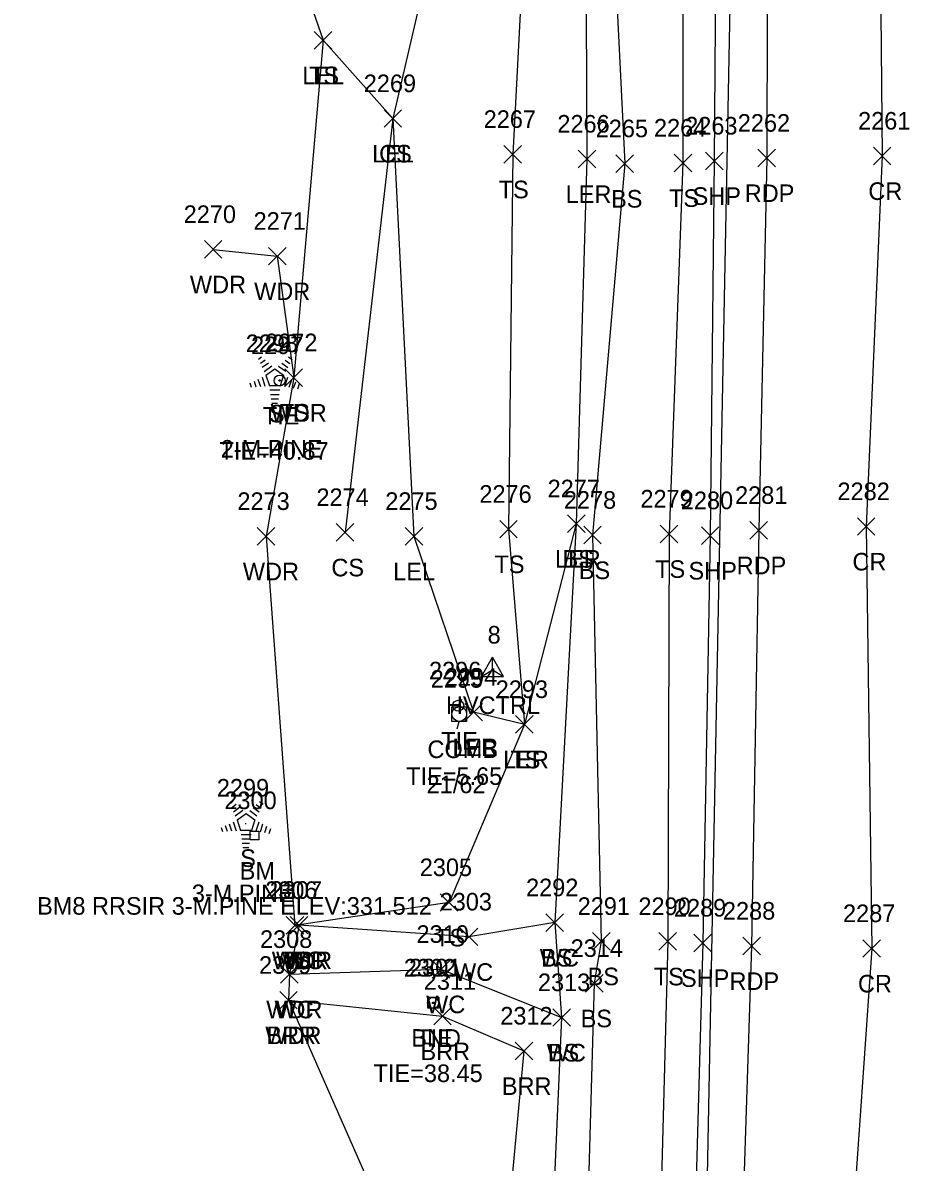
# Model space of a CAD drawing. Extents: x 1462089 to 1464015, y 730534 to 736144.
# Drawn here: x 1463126.5 to 1463227.3, y 734283.7 to 734413.3 of the extents above; entities that cross this region are included whole.
import ezdxf

# ---------------------------------------------------------------- set-up
doc = ezdxf.new("R2010")
doc.units = 0
for name, color, linetype in [('C_A', 7, 'Continuous'), ('C_C', 7, 'Continuous'), ('C_I', 7, 'Continuous'), ('CBP', 7, 'Continuous'), ('CPBM', 7, 'Continuous'), ('CPSM', 7, 'Continuous'), ('DCP', 7, 'Continuous'), ('L_A', 7, 'Continuous'), ('L_C', 7, 'Continuous'), ('L_I', 7, 'Continuous'), ('L_TIC', 7, 'Continuous'), ('LABL', 7, 'Continuous'), ('LARO', 7, 'Continuous'), ('LAWA', 7, 'Continuous'), ('LAWE', 7, 'Continuous'), ('LELB', 7, 'Continuous'), ('LTC', 7, 'Continuous'), ('M_A', 7, 'Continuous'), ('M_I', 7, 'Continuous'), ('MHBP', 7, 'Continuous'), ('P_A', 7, 'Continuous'), ('P_I', 7, 'Continuous'), ('P_TIC', 7, 'Continuous'), ('PET', 7, 'Continuous'), ('PRC', 7, 'Continuous'), ('PSP', 7, 'Continuous'), ('U_A', 7, 'Continuous'), ('U_C', 7, 'Continuous'), ('U_I', 7, 'Continuous'), ('UP', 7, 'Continuous')]:
    doc.layers.add(name, color=color, linetype=linetype)

msp = doc.modelspace()

# ---------------------------------------------------------------- linework, layer by layer
at = {"layer": 'CBP'}
for centre, radius in [((1463155.69, 734372.59), 0.625), ((1463155.69, 734372.59), 0.0833), ((1463175.99, 734335.61), 0.625), ((1463175.99, 734335.61), 0.0833), ((1463173.14, 734301.82), 0.625), ((1463173.14, 734301.82), 0.0833)]:
    msp.add_circle(centre, radius, dxfattribs=at)
at = {"layer": 'CPBM'}
for p, q in [((1463152.32, 734320.35), (1463152.32, 734321.35)), ((1463152.32, 734321.35), (1463153.32, 734321.35)), ((1463152.82, 734320.85), (1463152.82, 734320.85)), ((1463152.82, 734320.85), (1463152.82, 734320.85)), ((1463153.32, 734321.35), (1463153.32, 734320.35)), ((1463153.32, 734320.35), (1463152.32, 734320.35))]:
    msp.add_line(p, q, dxfattribs=at)
at = {"layer": 'CPSM'}
for p, q in [((1463178.66, 734338.95), (1463179.91, 734341.12)), ((1463181.16, 734338.95), (1463179.91, 734341.12)), ((1463179.91, 734339.68), (1463179.91, 734341.12)), ((1463178.66, 734338.95), (1463179.91, 734339.68)), ((1463178.66, 734338.95), (1463181.16, 734338.95)), ((1463179.91, 734339.68), (1463179.91, 734339.68)), ((1463179.91, 734339.68), (1463181.16, 734338.95))]:
    msp.add_line(p, q, dxfattribs=at)
at = {"layer": 'DCP'}
msp.add_lwpolyline([(1463208.21, 734483.63), (1463199.06, 734012.28)], dxfattribs=at)
at = {"layer": 'L_TIC'}
for points in [[(1463159.62, 734410.28), (1463161.62, 734412.28)], [(1463161.62, 734410.28), (1463159.62, 734412.28)], [(1463159.62, 734410.28), (1463161.62, 734412.28)], [(1463161.62, 734410.28), (1463159.62, 734412.28)], [(1463167.56, 734401.38), (1463169.56, 734403.38)], [(1463169.56, 734401.38), (1463167.56, 734403.38)], [(1463167.56, 734401.38), (1463169.56, 734403.38)], [(1463169.56, 734401.38), (1463167.56, 734403.38)], [(1463181.19, 734397.31), (1463183.19, 734399.31)], [(1463183.19, 734397.31), (1463181.19, 734399.31)], [(1463189.63, 734396.78), (1463191.63, 734398.78)], [(1463191.63, 734396.78), (1463189.63, 734398.78)], [(1463193.94, 734396.25), (1463195.94, 734398.25)], [(1463195.94, 734396.25), (1463193.94, 734398.25)], [(1463200.56, 734396.33), (1463202.56, 734398.33)], [(1463202.56, 734396.33), (1463200.56, 734398.33)], [(1463147.12, 734386.5), (1463149.12, 734388.5)], [(1463149.12, 734386.5), (1463147.12, 734388.5)], [(1463154.42, 734385.73), (1463156.42, 734387.73)], [(1463156.42, 734385.73), (1463154.42, 734387.73)], [(1463156.29, 734371.92), (1463158.29, 734373.92)], [(1463158.29, 734371.92), (1463156.29, 734373.92)], [(1463156.29, 734371.92), (1463158.29, 734373.92)], [(1463158.29, 734371.92), (1463156.29, 734373.92)], [(1463180.71, 734354.69), (1463182.71, 734356.69)], [(1463182.71, 734354.69), (1463180.71, 734356.69)], [(1463188.42, 734355.31), (1463190.42, 734357.31)], [(1463190.42, 734355.31), (1463188.42, 734357.31)], [(1463188.42, 734355.31), (1463190.42, 734357.31)], [(1463190.42, 734355.31), (1463188.42, 734357.31)], [(1463153.14, 734353.87), (1463155.14, 734355.87)], [(1463155.14, 734353.87), (1463153.14, 734355.87)], [(1463162.13, 734354.32), (1463164.13, 734356.32)], [(1463164.13, 734354.32), (1463162.13, 734356.32)], [(1463169.96, 734353.88), (1463171.96, 734355.88)], [(1463171.96, 734353.88), (1463169.96, 734355.88)], [(1463190.27, 734354.01), (1463192.27, 734356.01)], [(1463192.27, 734354.01), (1463190.27, 734356.01)], [(1463198.98, 734354.15), (1463200.98, 734356.15)], [(1463200.98, 734354.15), (1463198.98, 734356.15)], [(1463176.74, 734333.88), (1463178.74, 734335.88)], [(1463178.74, 734333.88), (1463176.74, 734335.88)], [(1463176.74, 734333.88), (1463178.74, 734335.88)], [(1463178.74, 734333.88), (1463176.74, 734335.88)], [(1463182.52, 734332.49), (1463184.52, 734334.49)], [(1463184.52, 734332.49), (1463182.52, 734334.49)], [(1463182.52, 734332.49), (1463184.52, 734334.49)], [(1463184.52, 734332.49), (1463182.52, 734334.49)], [(1463173.96, 734312.24), (1463175.96, 734314.24)], [(1463175.96, 734312.24), (1463173.96, 734314.24)], [(1463156.43, 734309.64), (1463158.43, 734311.64)], [(1463158.43, 734309.64), (1463156.43, 734311.64)], [(1463156.43, 734309.64), (1463158.43, 734311.64)], [(1463158.43, 734309.64), (1463156.43, 734311.64)], [(1463156.9, 734309.66), (1463158.9, 734311.66)], [(1463158.9, 734309.66), (1463156.9, 734311.66)], [(1463156.9, 734309.66), (1463158.9, 734311.66)], [(1463158.9, 734309.66), (1463156.9, 734311.66)], [(1463185.97, 734309.95), (1463187.97, 734311.95)], [(1463187.97, 734309.95), (1463185.97, 734311.95)], [(1463185.97, 734309.95), (1463187.97, 734311.95)], [(1463187.97, 734309.95), (1463185.97, 734311.95)], [(1463176.22, 734308.33), (1463178.22, 734310.33)], [(1463178.22, 734308.33), (1463176.22, 734310.33)], [(1463191.27, 734307.83), (1463193.27, 734309.83)], [(1463193.27, 734307.83), (1463191.27, 734309.83)], [(1463198.83, 734307.81), (1463200.83, 734309.81)], [(1463200.83, 734307.81), (1463198.83, 734309.81)], [(1463173.03, 734304.65), (1463175.03, 734306.65)], [(1463175.03, 734304.65), (1463173.03, 734306.65)], [(1463155.79, 734304.07), (1463157.79, 734306.07)], [(1463157.79, 734304.07), (1463155.79, 734306.07)], [(1463155.79, 734304.07), (1463157.79, 734306.07)], [(1463157.79, 734304.07), (1463155.79, 734306.07)], [(1463190.47, 734303.05), (1463192.47, 734305.05)], [(1463192.47, 734303.05), (1463190.47, 734305.05)], [(1463155.69, 734301.13), (1463157.69, 734303.13)], [(1463157.69, 734301.13), (1463155.69, 734303.13)], [(1463155.69, 734301.13), (1463157.69, 734303.13)], [(1463157.69, 734301.13), (1463155.69, 734303.13)], [(1463173.21, 734299.31), (1463175.21, 734301.31)], [(1463175.21, 734299.31), (1463173.21, 734301.31)], [(1463186.75, 734299.16), (1463188.75, 734301.16)], [(1463188.75, 734299.16), (1463186.75, 734301.16)], [(1463186.75, 734299.16), (1463188.75, 734301.16)], [(1463188.75, 734299.16), (1463186.75, 734301.16)], [(1463182.47, 734295.36), (1463184.47, 734297.36)], [(1463184.47, 734295.36), (1463182.47, 734297.36)]]:
    msp.add_lwpolyline(points, dxfattribs=at)
at = {"layer": 'LABL'}
msp.add_lwpolyline([(1463156.69, 734302.13), (1463174.21, 734300.31), (1463183.47, 734296.36), (1463181.09, 734271.11), (1463181.93, 734223), (1463178.85, 734177.9), (1463178.45, 734143.72), (1463169.26, 734138.24), (1463157.46, 734125.42), (1463144.39, 734102.43)], dxfattribs=at)
at = {"layer": 'LARO'}
for points in [[(1463147.4, 734662.67), (1463157.46, 734664.77), (1463169.03, 734661.82), (1463169.68, 734646.7), (1463182.2, 734627.23), (1463187.8, 734600.17), (1463188.26, 734544.08), (1463183.83, 734520.03), (1463176.69, 734515.3), (1463169.22, 734500.9), (1463169.8, 734483.47), (1463167.02, 734456.28), (1463176.84, 734437.92), (1463184.12, 734434.72), (1463190.48, 734431.13), (1463190.63, 734397.78), (1463189.42, 734356.31), (1463183.52, 734333.49), (1463177.74, 734334.88)], [(1463143.95, 734520.52), (1463142.85, 734496.85), (1463155.61, 734488.43), (1463144.85, 734456.52), (1463160.62, 734411.28), (1463168.56, 734402.38), (1463170.96, 734354.88), (1463177.74, 734334.88)]]:
    msp.add_lwpolyline(points, dxfattribs=at)
at = {"layer": 'LAWA'}
msp.add_lwpolyline([(1463148.12, 734387.5), (1463155.42, 734386.73), (1463157.29, 734372.92), (1463154.14, 734354.87), (1463157.43, 734310.64), (1463157.9, 734310.66), (1463156.79, 734305.07), (1463156.69, 734302.13), (1463169.77, 734272.41), (1463157.85, 734224.06), (1463161.29, 734206.99), (1463143.39, 734203.85), (1463126.47, 734185.65), (1463137.14, 734130.78), (1463144.39, 734102.43), (1463152.2, 734075.02), (1463142.97, 734026.1), (1463140.98, 733987.76), (1463154.22, 733983.37), (1463156.8, 733967.66), (1463142.94, 733971.97)], dxfattribs=at)
at = {"layer": 'LAWE'}
for points in [[(1463186.97, 734310.95), (1463177.22, 734309.33), (1463157.9, 734310.66)], [(1463156.79, 734305.07), (1463174.03, 734305.65), (1463187.75, 734300.16)]]:
    msp.add_lwpolyline(points, dxfattribs=at)
at = {"layer": 'LELB'}
for points in [[(1463188.62, 734799.74), (1463189.23, 734750.9), (1463189.74, 734700.69), (1463192.42, 734649.85), (1463191, 734599.71), (1463193.42, 734544.23), (1463196.71, 734496.43), (1463196.17, 734489.61), (1463194.29, 734482.61), (1463193.43, 734453.88), (1463193.28, 734430.96), (1463194.94, 734397.25), (1463191.27, 734355.01), (1463192.27, 734308.83), (1463191.47, 734304.05), (1463190.52, 734270.68), (1463189.48, 734220.76), (1463188.7, 734176.43), (1463187.31, 734119.86), (1463187.93, 734073.26), (1463188.66, 734026.72), (1463187.05, 734012.08), (1463189.61, 733964.42)], [(1463195.34, 734798.31), (1463197.41, 734750.53), (1463197.46, 734700.17), (1463198.58, 734651.04), (1463199.21, 734598.9), (1463200.2, 734544.23), (1463202.14, 734496.43), (1463201.54, 734449.41), (1463201.56, 734397.33), (1463199.98, 734355.15), (1463199.83, 734308.81), (1463198.79, 734268.98), (1463198.11, 734220.24), (1463196.93, 734175.14), (1463195.85, 734119.26), (1463193.82, 734072.07), (1463194.4, 734026.45), (1463194.59, 734010.55), (1463192.58, 733964.29), (1463190.31, 733917.66)], [(1463178.57, 734776.69), (1463177.31, 734753.5), (1463179.18, 734700.8), (1463180.32, 734646.66), (1463182.2, 734627.23), (1463182.7, 734603.79), (1463184.28, 734596.53), (1463183.86, 734543.96), (1463183.83, 734520.03), (1463183.36, 734481.92), (1463182.16, 734457.78), (1463184.12, 734434.72), (1463182.19, 734398.31), (1463181.71, 734355.69), (1463183.52, 734333.49), (1463174.96, 734313.24), (1463157.43, 734310.64)], [(1463182.7, 734603.79), (1463180.76, 734596.84), (1463172.86, 734543.3), (1463176.69, 734515.3), (1463177.02, 734482.59), (1463176.19, 734457.19), (1463176.84, 734437.92), (1463168.56, 734402.38), (1463163.13, 734355.32)], [(1463160.62, 734411.28), (1463157.29, 734372.92)], [(1463189.42, 734356.31), (1463186.97, 734310.95), (1463187.75, 734300.16), (1463186.45, 734270.72), (1463186.26, 734221.6), (1463184.59, 734177.13), (1463184.44, 734120.4), (1463183.66, 734072.96), (1463185.97, 734027.2), (1463185.64, 734017.64), (1463181.98, 734013.82), (1463182.38, 734009.37), (1463185.74, 734008.63), (1463186.1, 733963.74), (1463187.32, 733917.63), (1463182.85, 733886.22), (1463182.95, 733866.86), (1463182.65, 733862.97), (1463181.59, 733831.54)]]:
    msp.add_lwpolyline(points, dxfattribs=at)
at = {"layer": 'LTC'}
for p, q in [((1463153.28, 734375.03), (1463153.63, 734375.29)), ((1463153.49, 734374.56), (1463154.02, 734374.95)), ((1463156.31, 734374.92), (1463156.86, 734374.52)), ((1463156.68, 734375.27), (1463157.1, 734374.97)), ((1463153.7, 734374.1), (1463154.4, 734374.61)), ((1463153.91, 734373.63), (1463154.79, 734374.27)), ((1463154.13, 734373.18), (1463155.15, 734373.91)), ((1463155.15, 734373.91), (1463156.14, 734373.19)), ((1463155.57, 734374.22), (1463156.37, 734373.64)), ((1463155.94, 734374.57), (1463156.62, 734374.08)), ((1463152.31, 734372.31), (1463152.46, 734371.84)), ((1463152.77, 734372.53), (1463152.98, 734371.87)), ((1463153.22, 734372.74), (1463153.49, 734371.91)), ((1463153.68, 734372.96), (1463154.01, 734371.94)), ((1463154.13, 734373.18), (1463154.52, 734371.98)), ((1463156.14, 734373.19), (1463155.75, 734371.98)), ((1463156.58, 734372.92), (1463156.24, 734371.88)), ((1463157.02, 734372.67), (1463156.74, 734371.78)), ((1463157.47, 734372.42), (1463157.23, 734371.69)), ((1463155.75, 734371.98), (1463154.52, 734371.98)), ((1463155.71, 734371.48), (1463154.57, 734371.48)), ((1463155.63, 734370.98), (1463154.64, 734370.98)), ((1463157.91, 734372.17), (1463157.73, 734371.59)), ((1463155.55, 734370.48), (1463154.71, 734370.48)), ((1463155.46, 734369.98), (1463154.79, 734369.98)), ((1463150.01, 734324.49), (1463150.36, 734324.75)), ((1463150.22, 734324.02), (1463150.75, 734324.41)), ((1463153.03, 734324.38), (1463153.58, 734323.98)), ((1463153.4, 734324.73), (1463153.82, 734324.43)), ((1463150.43, 734323.56), (1463151.13, 734324.07)), ((1463150.64, 734323.09), (1463151.51, 734323.73)), ((1463150.86, 734322.64), (1463151.87, 734323.37)), ((1463151.87, 734323.37), (1463152.87, 734322.65)), ((1463152.29, 734323.69), (1463153.1, 734323.1)), ((1463152.66, 734324.03), (1463153.34, 734323.54)), ((1463149.04, 734321.77), (1463149.19, 734321.3)), ((1463149.49, 734321.99), (1463149.71, 734321.33)), ((1463149.95, 734322.2), (1463150.22, 734321.37)), ((1463150.41, 734322.42), (1463150.74, 734321.4)), ((1463150.86, 734322.64), (1463151.25, 734321.44)), ((1463152.87, 734322.65), (1463152.48, 734321.44)), ((1463153.31, 734322.38), (1463152.97, 734321.34)), ((1463153.75, 734322.13), (1463153.46, 734321.24)), ((1463154.2, 734321.88), (1463153.96, 734321.15)), ((1463152.48, 734321.44), (1463151.25, 734321.44)), ((1463152.44, 734320.94), (1463151.29, 734320.94)), ((1463152.36, 734320.44), (1463151.37, 734320.44)), ((1463154.64, 734321.63), (1463154.45, 734321.05)), ((1463152.27, 734319.94), (1463151.44, 734319.94)), ((1463152.19, 734319.44), (1463151.51, 734319.44))]:
    msp.add_line(p, q, dxfattribs=at)
at = {"layer": 'MHBP'}
msp.add_lwpolyline([(1463172.55, 734302.47), (1463173.8, 734302.47), (1463173.8, 734301.22), (1463172.55, 734301.22)], close=True, dxfattribs=at)
msp.add_circle((1463173.17, 734301.84), 0.0833, dxfattribs=at)
at = {"layer": 'P_TIC'}
for points in [[(1463204.12, 734396.56), (1463206.12, 734398.56)], [(1463206.12, 734396.56), (1463204.12, 734398.56)], [(1463210.09, 734396.88), (1463212.09, 734398.88)], [(1463212.09, 734396.88), (1463210.09, 734398.88)], [(1463223.21, 734397.12), (1463225.21, 734399.12)], [(1463225.21, 734397.12), (1463223.21, 734399.12)], [(1463221.39, 734354.99), (1463223.39, 734356.99)], [(1463223.39, 734354.99), (1463221.39, 734356.99)], [(1463203.65, 734353.96), (1463205.65, 734355.96)], [(1463205.65, 734353.96), (1463203.65, 734355.96)], [(1463209.17, 734354.56), (1463211.17, 734356.56)], [(1463211.17, 734354.56), (1463209.17, 734356.56)], [(1463202.8, 734307.64), (1463204.8, 734309.64)], [(1463204.8, 734307.64), (1463202.8, 734309.64)], [(1463208.36, 734307.29), (1463210.36, 734309.29)], [(1463210.36, 734307.29), (1463208.36, 734309.29)], [(1463222.02, 734307.01), (1463224.02, 734309.01)], [(1463224.02, 734307.01), (1463222.02, 734309.01)]]:
    msp.add_lwpolyline(points, dxfattribs=at)
at = {"layer": 'PET'}
msp.add_lwpolyline([(1463204.71, 734797.84), (1463205.78, 734749.61), (1463206.44, 734700.37), (1463207.91, 734653.17), (1463208.96, 734598.74), (1463210.17, 734544.3), (1463210.74, 734497.48), (1463211.21, 734449.42), (1463211.09, 734397.88), (1463210.17, 734355.56), (1463209.36, 734308.29), (1463208.04, 734267.48), (1463207.44, 734219.42), (1463205.88, 734174.98), (1463204.27, 734119.17), (1463203.71, 734073.3), (1463203.1, 734019.17), (1463201.74, 733964.33)], dxfattribs=at)
at = {"layer": 'PRC'}
msp.add_lwpolyline([(1463217.11, 734797.78), (1463218.92, 734749.04), (1463217.99, 734700.8), (1463220.46, 734654.03), (1463220.81, 734599.08), (1463223.52, 734546), (1463222.51, 734496.9), (1463223.72, 734451.06), (1463224.21, 734398.12), (1463222.39, 734355.99), (1463223.02, 734308.01), (1463220.18, 734267.3), (1463222.37, 734218.38), (1463218.64, 734173.78), (1463216.82, 734118.18), (1463215.37, 734073.48), (1463215.19, 734017.4), (1463213.25, 733964.17)], dxfattribs=at)
at = {"layer": 'PSP'}
msp.add_lwpolyline([(1463199.84, 734798.03), (1463200.23, 734750.21), (1463201.04, 734700.38), (1463202.35, 734652.01), (1463203.05, 734599.23), (1463204.56, 734544.33), (1463205.11, 734496.59), (1463205.48, 734449.4), (1463205.12, 734397.56), (1463204.65, 734354.96), (1463203.8, 734308.64), (1463202.66, 734268.21), (1463201.74, 734219.53), (1463200.48, 734174.61), (1463198.94, 734119.22), (1463197.74, 734073.05), (1463196.88, 734018.95), (1463195.12, 733964.59)], dxfattribs=at)
at = {"layer": 'UP'}
for p, q in [((1463176.37, 734336.32), (1463176.12, 734335.49)), ((1463175.28, 734333.82), (1463175.28, 734335.49)), ((1463175.28, 734335.49), (1463176.95, 734335.49)), ((1463176.95, 734335.49), (1463176.95, 734333.82)), ((1463176.95, 734333.82), (1463175.28, 734333.82)), ((1463175.87, 734332.99), (1463176.12, 734333.82)), ((1463176.12, 734334.66), (1463176.12, 734334.66))]:
    msp.add_line(p, q, dxfattribs=at)
msp.add_circle((1463176.12, 734334.66), 0.833, dxfattribs=at)

# ---------------------------------------------------------------- texts
at = {"layer": 'C_A'}
for s, p in [('TIE', (1463153.77, 734367.59)), ('HVCTRL', (1463174.6, 734334.67)), ('TIE', (1463174.07, 734330.61)), ('BM', (1463151.14, 734315.85)), ('TIE', (1463171.22, 734296.82))]:
    msp.add_text(s, height=2, dxfattribs=at).set_placement(p)
at = {"layer": 'C_C'}
for s, p in [('TIE=40.87', (1463148.84, 734363.59)), ('TIE=5.65', (1463170.07, 734326.61)), ('BM8 RRSIR 3-M.PINE ELEV:331.512', (1463128.1, 734311.85)), ('TIE=38.45', (1463166.37, 734292.82))]:
    msp.add_text(s, height=2, dxfattribs=at).set_placement(p)
at = {"layer": 'C_I'}
for s, p in [('2297', (1463152.43, 734375.59)), ('8', (1463179.34, 734342.68)), ('2296', (1463172.67, 734338.61)), ('2300', (1463149.4, 734323.85)), ('2302', (1463169.81, 734304.82))]:
    msp.add_text(s, height=2, dxfattribs=at).set_placement(p)
at = {"layer": 'L_A'}
for s, p in [('LEL', (1463158.26, 734406.28)), ('TS', (1463159.03, 734406.28)), ('LEL', (1463166.2, 734397.38)), ('CS', (1463167, 734397.38)), ('TS', (1463180.6, 734393.31)), ('LER', (1463188.21, 734392.78)), ('BS', (1463193.38, 734392.25)), ('TS', (1463199.97, 734392.33)), ('WDR', (1463145.48, 734382.5)), ('WDR', (1463152.78, 734381.73)), ('S', (1463154.47, 734367.82)), ('WDR', (1463154.65, 734367.92)), ('TS', (1463155.7, 734367.92)), ('LER', (1463187, 734351.31)), ('BS', (1463187.86, 734351.31)), ('WDR', (1463151.5, 734349.87)), ('CS', (1463161.57, 734350.32)), ('LEL', (1463168.6, 734349.88)), ('TS', (1463180.12, 734350.69)), ('BS', (1463189.71, 734350.01)), ('TS', (1463198.39, 734350.15)), ('LER', (1463175.32, 734329.88)), ('LEL', (1463175.38, 734329.88)), ('LER', (1463181.1, 734328.49)), ('TS', (1463181.92, 734328.49)), ('S', (1463151.2, 734317.28)), ('TS', (1463173.37, 734308.24)), ('WDR', (1463154.79, 734305.64)), ('WDR', (1463155.27, 734305.66)), ('TS', (1463155.84, 734305.64)), ('WC', (1463156.21, 734305.66)), ('WC', (1463185.27, 734305.95)), ('BS', (1463185.41, 734305.95)), ('WC', (1463175.52, 734304.33)), ('BS', (1463190.71, 734303.83)), ('TS', (1463198.24, 734303.81)), ('WC', (1463172.34, 734300.65)), ('WDR', (1463154.16, 734300.07)), ('WC', (1463155.1, 734300.07)), ('BS', (1463189.92, 734299.05)), ('WDR', (1463154.05, 734297.13)), ('BRR', (1463154.18, 734297.13)), ('BRR', (1463171.7, 734295.31)), ('WC', (1463186.06, 734295.16)), ('BS', (1463186.19, 734295.16)), ('BRR', (1463180.96, 734291.36))]:
    msp.add_text(s, height=2, dxfattribs=at).set_placement(p)
at = {"layer": 'L_C'}
for s, p in [('2-M.PINE', (1463148.98, 734363.82)), ('3-M.PINE', (1463145.7, 734313.28))]:
    msp.add_text(s, height=2, dxfattribs=at).set_placement(p)
at = {"layer": 'L_I'}
for s, p in [('2269', (1463165.25, 734405.38)), ('2269', (1463165.25, 734405.38)), ('2267', (1463178.89, 734401.31)), ('2266', (1463187.27, 734400.78)), ('2265', (1463191.63, 734400.25)), ('2264', (1463198.26, 734400.33)), ('2270', (1463144.77, 734390.5)), ('2271', (1463152.72, 734389.73)), ('2298', (1463151.83, 734375.82)), ('2272', (1463154.03, 734375.92)), ('2272', (1463154.03, 734375.92)), ('2276', (1463178.4, 734358.69)), ('2277', (1463186.16, 734359.31)), ('2277', (1463186.16, 734359.31)), ('2273', (1463150.88, 734357.87)), ('2274', (1463159.87, 734358.32)), ('2275', (1463167.7, 734357.88)), ('2278', (1463188.01, 734358.01)), ('2279', (1463196.72, 734358.15)), ('2294', (1463174.48, 734337.88)), ('2294', (1463174.48, 734337.88)), ('2293', (1463180.26, 734336.49)), ('2293', (1463180.26, 734336.49)), ('2299', (1463148.54, 734325.28)), ('2305', (1463171.62, 734316.24)), ('2306', (1463154.04, 734313.64)), ('2306', (1463154.04, 734313.64)), ('2307', (1463154.56, 734313.66)), ('2307', (1463154.56, 734313.66)), ('2292', (1463183.71, 734313.95)), ('2292', (1463183.71, 734313.95)), ('2303', (1463173.88, 734312.33)), ('2291', (1463189.58, 734311.83)), ('2290', (1463196.49, 734311.81)), ('2308', (1463153.45, 734308.07)), ('2308', (1463153.45, 734308.07)), ('2310', (1463171.25, 734308.65)), ('2314', (1463188.78, 734307.05)), ('2309', (1463153.34, 734305.13)), ('2309', (1463153.34, 734305.13)), ('2311', (1463172.08, 734303.31)), ('2313', (1463185.06, 734303.16)), ('2313', (1463185.06, 734303.16)), ('2312', (1463180.78, 734299.36))]:
    msp.add_text(s, height=2, dxfattribs=at).set_placement(p)
at = {"layer": 'LTC'}
for p in [(1463155.03, 734372.93), (1463151.75, 734322.39)]:
    msp.add_text('.', height=1.04, rotation=270, dxfattribs=at).set_placement(p)
at = {"layer": 'M_A'}
msp.add_text('BND', height=2, dxfattribs=at).set_placement((1463170.66, 734296.84))
at = {"layer": 'M_I'}
msp.add_text('2301', height=2, dxfattribs=at).set_placement((1463170.4, 734304.84))
at = {"layer": 'P_A'}
for s, p in [('SHP', (1463202.65, 734392.56)), ('RDP', (1463208.58, 734392.88)), ('CR', (1463222.64, 734393.12)), ('CR', (1463220.83, 734350.99)), ('SHP', (1463202.19, 734349.96)), ('RDP', (1463207.66, 734350.56)), ('SHP', (1463201.33, 734303.64)), ('RDP', (1463206.85, 734303.29)), ('CR', (1463221.46, 734303.01))]:
    msp.add_text(s, height=2, dxfattribs=at).set_placement(p)
at = {"layer": 'P_I'}
for s, p in [('2263', (1463201.81, 734400.56)), ('2262', (1463207.79, 734400.88)), ('2261', (1463221.47, 734401.12)), ('2281', (1463207.48, 734358.56)), ('2282', (1463219.13, 734358.99)), ('2280', (1463201.31, 734357.96)), ('2289', (1463200.53, 734311.64)), ('2288', (1463206.1, 734311.29)), ('2287', (1463219.76, 734311.01))]:
    msp.add_text(s, height=2, dxfattribs=at).set_placement(p)
at = {"layer": 'U_A'}
msp.add_text('COMB', height=2, dxfattribs=at).set_placement((1463172.5, 734329.66))
at = {"layer": 'U_C'}
msp.add_text('21/62', height=2, dxfattribs=at).set_placement((1463172.4, 734325.66))
at = {"layer": 'U_I'}
msp.add_text('2295', height=2, dxfattribs=at).set_placement((1463172.86, 734337.66))

doc.saveas('drawing.dxf')
